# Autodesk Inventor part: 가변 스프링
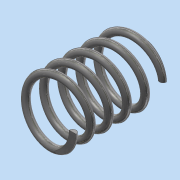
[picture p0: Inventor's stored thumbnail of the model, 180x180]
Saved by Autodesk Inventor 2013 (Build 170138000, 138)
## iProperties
Created: 2018-10
Part Number: 가변 스프링
Material: 스테인리스강
Document SubType Name: Modeling
Designer: Administrator
Density: 8.08 g/cm^3
Mass: 6.26905 g
Surface Area: 15.7665 cm^2
Volume: 0.775873 cm^3
Author: Administrator
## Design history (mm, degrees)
sketch "스케치1"
  geometry: L1 (0, 0)-(0, 25.941); L2 (0.539, 0)-(8, 0); L3 (0, 25.941)-(8, 25.941); C1 r 1 at (8, 0)
  constraints: 6 end point, 1 centre point, 1 horizontal alignment, 1 parallel, 1 perpendicular, 1 vertical
  dimensions: "d0" = 25.94125 distance of L1.start L1.end (derived); "d1" = 2 diameter of C1; "d2" = 16 diameter of L2.end L1; "d3" = 8 distance of L1.end L3.end
feature "코일1" sketch "스케치1" pitch "d4" = 10; turns "d6" = 5; dims "d5" = 25.94125 (= d0), "d7" = 0, angle "d8" = 90 deg, angle "d9" = 90 deg, "d10" = 0, "d11" = 0
sketch "스케치2"
  geometry: L1 (25.941, 11)-(0, 11); L2 (0, 11)-(0, -11); L3 (0, -11)-(25.941, -11); L4 (25.941, -11)-(25.941, 11); 2 further points
  constraints: 8 end point, 2 parallel, 1 coincident, 1 horizontal, 1 midpoint, 1 perpendicular
  dimensions: "d12" = 25.94125 distance of L3.end L2.end (derived); "d13" = 22 distance of L2.end L1.end
extrude "돌출1" sketch "스케치2" stored distance "d14" = 0; taper "d15" = 0 deg
node "솔리드1"
